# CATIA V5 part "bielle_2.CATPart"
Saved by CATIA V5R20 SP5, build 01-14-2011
Part number: bielle_2
Bounding box of the stored display mesh (mm): x 0 to 15, y -29.989 to 29.989, z -29.951 to 110
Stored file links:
  U:\2A\IAO\ThinkMotion\bielle_2.CATPart
  U:\2A\IAO\ThinkMotion\MECANISME 1517.CATProduct
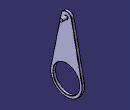
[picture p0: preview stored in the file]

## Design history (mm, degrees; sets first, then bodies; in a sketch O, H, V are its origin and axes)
Set1
  Plane1 "Plan_ref": linked copy from another document
  Point1: linked copy from another document
  Point2: linked copy from another document
Body1 (main body)
  Sketch1 on Plane1, origin (0, 0, 0), H (0, 1, 0), V (0, 0, 1)
    circle A1 centre (0, 0) radius 25
    point P1 (0, 0)
    reference projected point E1 (0, 0) from Point1
    arc A2 centre (0, 100) radius 10 from (-9.798, 102) to (9.798, 102) cw
    point P6 (0, 100)
    reference projected point E2 (0, 100) from Point2
    arc A3 centre (0, 0) radius 30 from (-29.3939, 6) to (29.3939, 6) ccw
    point P7 (0, 0)
    reference projected point E3 (0, 0) from Point1
    line L1 (29.3939, 6) -> (9.798, 102)
    line L2 (-29.3939, 6) -> (-9.798, 102)
    radius A1 = 25
    distance A3 A1 = 5
    radius A2 = 10
    coincidence: P1 V, P1 E1, P6 E2, P7 E3
    tangency: L1 A3, A2 L1, A2 L2, L2 A3
  Pad1: profile Sketch1, direction (1, 0, 0), length 5
  Sketch2 on Plane1, origin (0, 0, 0), H (0, 1, 0), V (0, 0, 1)
    circle A1 centre (0, 100) radius 3
    point P1 (0, 100)
    reference projected point E1 (0, 100) from Point2
    radius A1 = 3
    coincidence: P1 V, P1 E1
  Pad2: profile Sketch2, direction (1, 0, 0), length 15
  Fillet1: radius 0.5, on end face of Pad1; face of Pad2; face of Pad2 from Sketch2.A1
